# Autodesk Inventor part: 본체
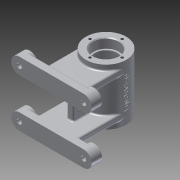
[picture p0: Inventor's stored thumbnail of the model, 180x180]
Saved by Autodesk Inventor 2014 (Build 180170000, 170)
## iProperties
Created: 2015-11
Part Number: 본체
Material: Aluminum 6061
Document SubType Name: Modeling
Designer: user
Mass: 357.945 g
Surface Area: 464.058 cm^2
Volume: 132.083 cm^3
Density: 2.71 g/cm^3
Appearance: Aluminum - Flat
Author: user
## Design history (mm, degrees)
sketch "Sketch1"
  geometry: C1 r 25 at (0, 0); 1 further point
  constraints: 1 centre point, 1 coincident
  dimensions: "d0" = 50 diameter of C1
extrude "Extrusion1" new body sketch "Sketch1" stored distance "d1" = 70; taper "d2" = 0 deg
workplane "Work Plane1"
sketch "Sketch2"
  geometry: L1 (40, -40)-(-40, -40); L2 (-40, -40)-(-40, -20); L3 (-40, -20)-(40, -20); L4 (40, -20)-(40, -40); L5 (40, 20)-(-40, 20); L6 (-40, 20)-(-40, 40); L7 (-40, 40)-(40, 40); L8 (40, 40)-(40, 20); 3 further points
  constraints: 16 end point, 4 parallel, 2 equal length, 2 horizontal, 2 midpoint, 2 perpendicular, 2 vertical alignment
  dimensions: "d4" = 40 distance from line of L1 point (0, 0); "d5" = 20 distance of L1.end L2.end; "d6" = 80 distance of L1.start L1.end; "d7" = 40 distance from line of L7 point (0, 0)
extrude "Extrusion2" join sketch "Sketch2" distance "d8" = 10; taper "d9" = 0 deg
sketch "Sketch3"
  geometry: L1 (40, 20)-(40, 40) reference; L2 (-40, 40)-(-40, 20) reference; L3 (-40, -40)-(40, -40) reference; L4 (40, -40)-(40, -20) reference; L5 (40, -20)-(-40, -20) reference; L6 (-40, -20)-(-40, -40) reference; C1 r 10 at (40, 30); C2 r 10 at (-40, 30); C3 r 10 at (40, -30); C4 r 10 at (-40, -30); 1 further point
  constraints: 4 centre point, 4 midpoint
  dimensions: "d10" = 20 diameter of C1; "d11" = 20 diameter of C2; "d12" = 20 diameter of C3; "d13" = 20 diameter of C4
extrude "Extrusion3" join sketch "Sketch3" distance "d14" = 13; taper "d15" = 0 deg
sketch "Sketch4"
  geometry: L1 (40, -20)-(-40, -20) reference; L2 (25, -20)-(-25, -20); L3 (-25, -20)-(-25, -28); L4 (-25, -28)-(25, -28); L5 (25, -28)-(25, -20); L6 (25, 28)-(-25, 28); L7 (-25, 28)-(-25, 20); L8 (-25, 20)-(25, 20); L9 (25, 20)-(25, 28); L10 (40, 20)-(-40, 20) reference; 5 further points
  constraints: 16 end point, 4 midpoint, 4 parallel, 2 coincident, 2 horizontal, 2 perpendicular, 2 vertical alignment
  dimensions: "d16" = 8 distance of L8.end L6.start; "d17" = 8 distance of L4.end L2.start; "d18" = 50 distance of L3.end L4.end; "d19" = 50 distance of L6.start L6.end
extrude "Extrusion4" join sketch "Sketch4" stored distance "d20" = 13; taper "d21" = 0 deg
workplane "Work Plane2"
sketch "Sketch5"
  geometry: L1 (40, 20)-(-40, 20) reference; L2 (-40, -20)-(40, -20) reference; L3 (-4, 20)-(4, 20); L4 (4, 20)-(4, -20); L5 (4, -20)-(-4, -20); L6 (-4, -20)-(-4, 20); 2 further points
  constraints: 8 end point, 2 parallel, 2 point on line, 1 horizontal, 1 midpoint, 1 perpendicular, 1 vertical alignment
  dimensions: "d23" = 8 distance between parallel lines of L6 L4
extrude "Extrusion5" join sketch "Sketch5" stored distance "d24" = 13; taper "d25" = 0 deg
sketch "Sketch6"
  geometry: L1 (40, 0)-(0, 0) reference; L2 (40, 20.322)-(40, 0) reference; L3 (12, 6.5)-(28, 6.5); L4 (28, 13.5)-(12, 13.5); A1 r 3.5 centre (28, 10) between (28, 6.5) and (28, 13.5); A2 r 3.5 centre (12, 10) between (12, 13.5) and (12, 6.5); 2 further points
  constraints: 4 end point, 4 point on circle, 3 tangent, 2 centre point, 1 equal radius, 1 midpoint, 1 parallel, 1 perpendicular, 1 vertical alignment
  dimensions: "d26" = 23 dimension on A1 A2; "d27" = 3.5 radius of A1; "d28" = 10 distance from line of A1.centre L1
extrude "Extrusion6" cut sketch "Sketch6" stored distance "d29" = 13; taper "d30" = 0 deg
workplane "Work Plane3"
sketch "Sketch7"
  geometry: C1 r 5 at (0, 0); 1 further point
  constraints: 1 centre point, 1 coincident
  dimensions: "d32" = 10 diameter of C1
extrude "Extrusion7" join sketch "Sketch7" stored distance "d33" = 13; taper "d34" = 0 deg
sketch "Sketch8"
  geometry: C1 r 25 at (0, 0) reference; C2 r 16 at (0, 0)
  constraints: 1 centre point, 1 coincident
  dimensions: "d35" = 32 diameter of C2
extrude "Extrusion8" cut sketch "Sketch8" distance "d36" = 12; taper "d37" = 0 deg
sketch "Sketch9"
  geometry: C1 r 16 at (0, 0) reference; C2 r 14 at (0, 0)
  constraints: 1 centre point, 1 coincident
  dimensions: "d38" = 28 diameter of C2
extrude "Extrusion9" cut sketch "Sketch9" distance "d39" = 2; taper "d40" = 0 deg
sketch "Sketch10"
  geometry: C1 r 16 at (0, 0) reference; 1 further point
  constraints: 1 vertical alignment
  dimensions: "d41" = 20 distance of C1.centre point (0, 20)
hole "Hole1" sketch "Sketch10" at (0, 20) diameter "d42" = 3.242; stored, may be unused: countersink angle "d46" = 90 deg, drill point angle "d48" = 118 deg; dims "d43" = 8, "d44" = 4, "d45" = 2, "d47" = 10
pattern_circular "Circular Pattern1" dims angle "d50" = 360 deg
mirror "Mirror1"
sketch "Sketch11"
  geometry: C1 r 14 at (0, 0) reference; C2 r 21 at (0, 0)
  constraints: 1 centre point, 1 coincident
  dimensions: "d52" = 42 diameter of C2
extrude "Extrusion10" cut sketch "Sketch11" distance "d53" = 42; taper "d54" = 0 deg
sketch "Sketch12"
  geometry: L1 (0, 0)-(-12.5, -21.651); L2 (0, 0)-(25, 0); 2 further points
  constraints: 4 end point, 1 coincident, 1 equal length, 1 horizontal, 2 other
  dimensions: "d55" = 120 deg angle of L1 L2
workplane "Work Plane5"
  workplane "Work Plane4"
sketch "Sketch13"
  geometry: C1 r 6 at (0, 0); 1 further point
  constraints: 1 centre point, 1 coincident
  dimensions: "d57" = 12 diameter of C1
extrude "Extrusion11" join sketch "Sketch13" stored distance "d58" = 42; taper "d59" = 0 deg
sketch "Sketch14"
  geometry: C1 r 5 at (0, 0) reference; 1 further point
  constraints: 1 coincident
hole "Hole2" sketch "Sketch14" at (0, 0) diameter "d60" = 5.188; stored, may be unused: countersink angle "d64" = 90 deg, drill point angle "d66" = 118 deg; dims "d61" = 8, "d62" = 4, "d63" = 2, "d65" = 10
sketch "Sketch15"
  geometry: C1 r 6 at (0, 0) reference; 1 further point
  constraints: 1 coincident
hole "Hole3" sketch "Sketch15" at (0, 0) diameter "d67" = 5.188; stored, may be unused: countersink angle "d71" = 90 deg, drill point angle "d73" = 118 deg; dims "d68" = 8, "d69" = 4, "d70" = 2, "d72" = 10
workplane "Work Plane6"
sketch "Sketch16"
  geometry: L1 (25, 35)-(-25, 35) reference; 2 further points
  constraints: 1 other
  dimensions: "d75" = 35 distance from line of point (0, 0) L1; "d76" = 25 horizontal distance of point (0, 0) L1.start
emboss "Emboss1" sketch "Sketch16" dims "d0" = 50, "d77" = 0.5, "d78" = 0
sketch "Sketch17"
  geometry: C1 r 10 at (0, 0) reference; C2 r 10 at (80, 0) reference; C3 r 10 at (80, -60) reference; C4 r 10 at (0, -60) reference; 5 further points
  constraints: 4 coincident
hole "Hole4" sketch "Sketch17" at (80, 0), (0, 0), (0, -60), (80, -60) diameter "d79" = 6; stored, may be unused: countersink angle "d83" = 90 deg, drill point angle "d85" = 0 deg; dims "d80" = 8.608, "d81" = 12, "d82" = 4, "d84" = 4
fillet "Fillet1" dims "d86" = 2
fillet "Fillet2" dims "d87" = 2
fillet "Fillet3" dims "d88" = 2
fillet "Fillet4" dims "d89" = 2, "d90" = 0.3
chamfer "Chamfer1" distance "d91" = 1; stored, may be unused: second distance "d92" = 2, angle "d93" = 45 deg
chamfer "Chamfer2" distance "d94" = 1; stored, may be unused: second distance "d95" = 2, angle "d96" = 45 deg
fillet "Fillet5" dims "d97" = 3
body "Solid1"
node "Projected Loop1"
node "Projected Loop2"
node "Projected Loop3"
node "Projected Loop4"
node "Projected Loop5"
other parameters: "d3" = -68, "d22" = -45, "d31" = 28, "d56" = 3, "d74" = 25
